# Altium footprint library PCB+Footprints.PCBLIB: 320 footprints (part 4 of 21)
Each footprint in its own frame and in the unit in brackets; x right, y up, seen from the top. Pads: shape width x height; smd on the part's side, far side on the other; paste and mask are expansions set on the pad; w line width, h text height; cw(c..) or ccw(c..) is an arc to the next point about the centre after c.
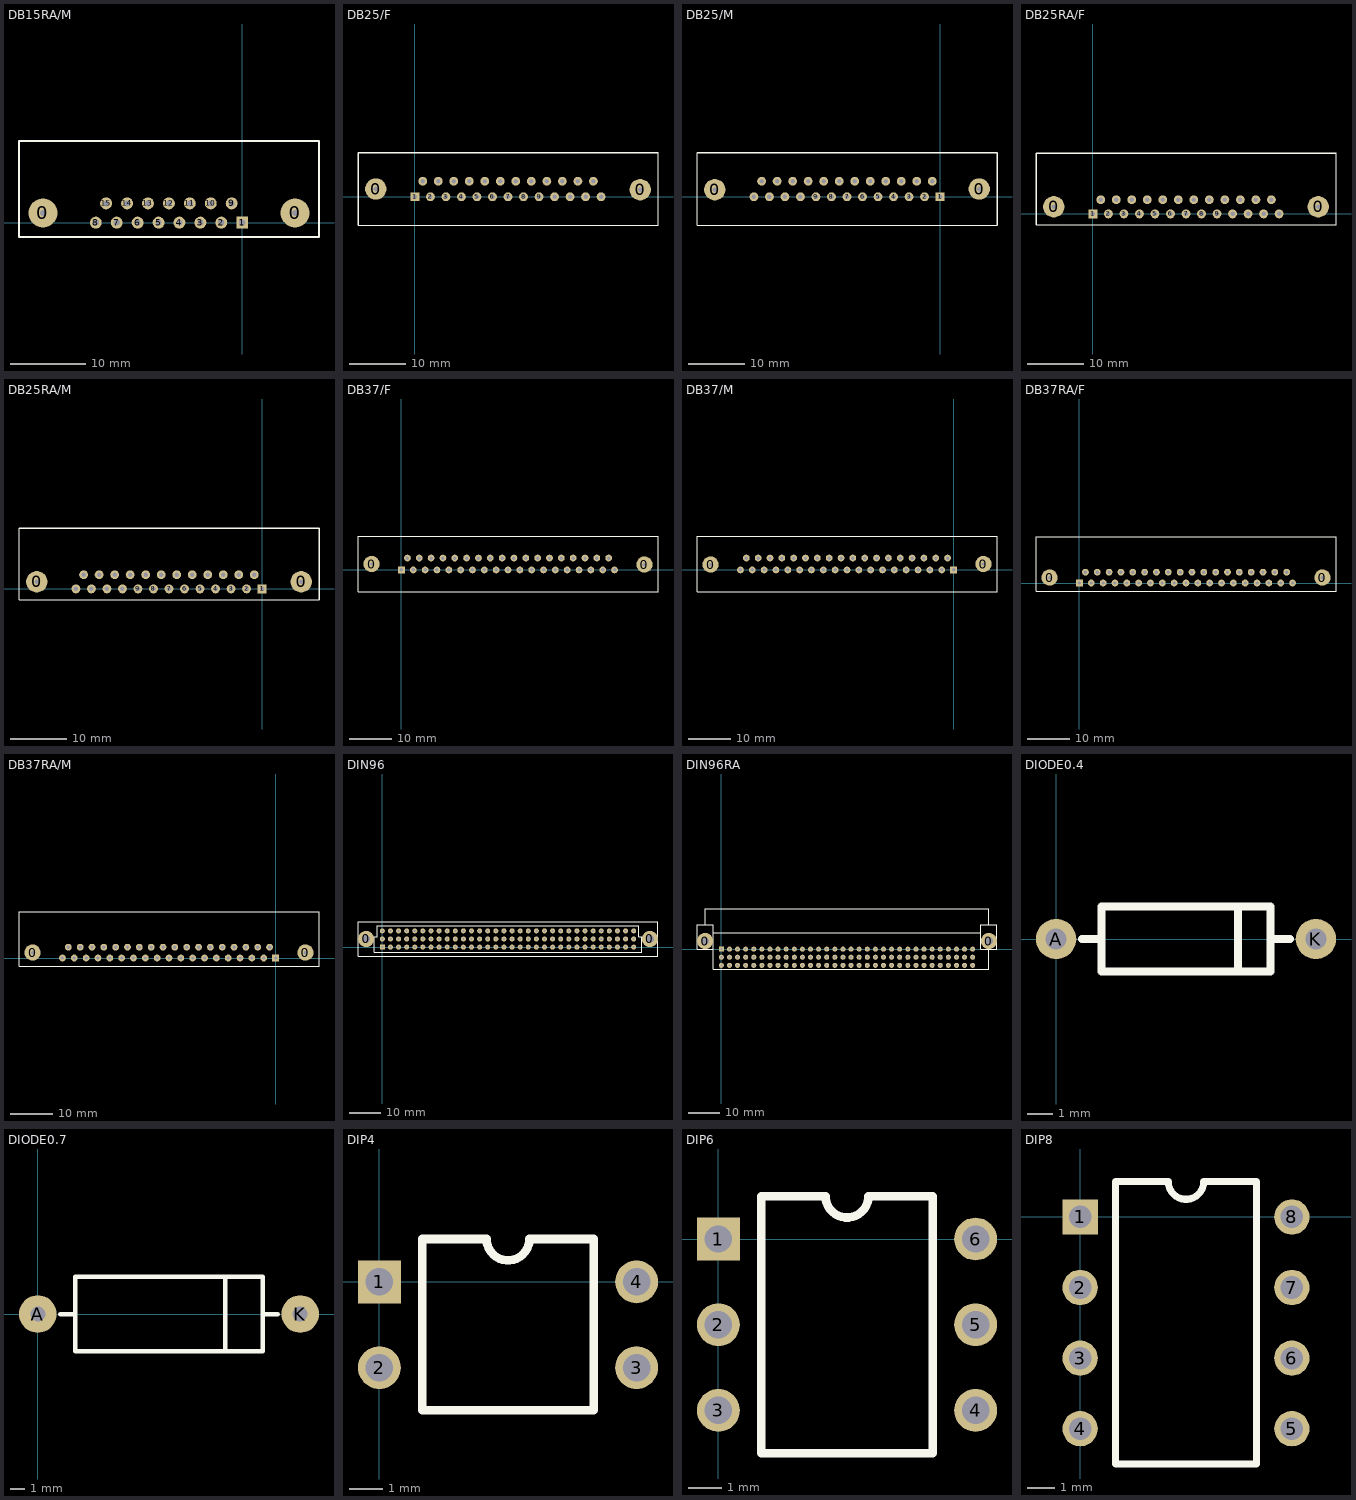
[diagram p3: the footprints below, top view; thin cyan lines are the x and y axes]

## DB15RA/M [mil]
pads (17):
  round 150 hole 32: 0(-1038,50) 0(275,50)
  rect 62x62 hole 32: 1(0,0)
  round 62 hole 32: 2(-109,0) 3(-218,0) 4(-327,0) 5(-436,0) 6(-545,0) 7(-654,0) 8(-763,0) 9(-55,100) 10(-164,100) 11(-273,100) 12(-382,100) 13(-491,100) 14(-600,100) 15(-709,100)
TopOverlay:
  lines w8: -1163,425 -1163,-75 400,-75
  lines w10: -1163,425 400,425 400,-75

## DB25/F [mil]
pads (27):
  round 150 hole 32: 0(-275,55) 0(1583,50)
  rect 62x62 hole 32: 1(0,0)
  round 62 hole 32: 2(109,0) 3(218,0) 4(327,0) 5(436,0) 6(545,0) 7(654,0) 8(763,0) 9(872,0) 10(981,0) 11(1090,0) 12(1199,0) 13(1308,0) 14(55,110) 15(164,110) 16(273,110) 17(382,110) 18(491,110) 19(600,110) 20(709,110) 21(818,110) 22(927,110) 23(1036,110) 24(1145,110) 25(1254,110)
TopOverlay:
  lines w8: -400,-200 1708,-200 1708,310
  lines w10: -400,-200 -400,310 1708,310

## DB25/M [mil]
pads (27):
  round 150 hole 32: 0(-1583,50) 0(275,55)
  rect 62x62 hole 32: 1(0,0)
  round 62 hole 32: 2(-109,0) 3(-218,0) 4(-327,0) 5(-436,0) 6(-545,0) 7(-654,0) 8(-763,0) 9(-872,0) 10(-981,0) 11(-1090,0) 12(-1199,0) 13(-1308,0) 14(-55,110) 15(-164,110) 16(-273,110) 17(-382,110) 18(-491,110) 19(-600,110) 20(-709,110) 21(-818,110) 22(-927,110) 23(-1036,110) 24(-1145,110) 25(-1254,110)
TopOverlay:
  lines w8: -1708,310 -1708,-200 400,-200
  lines w10: -1708,310 400,310 400,-200

## DB25RA/F [mil]
pads (27):
  round 150 hole 32: 0(-275,50) 0(1583,50)
  rect 62x62 hole 32: 1(0,0)
  round 62 hole 32: 2(109,0) 3(218,0) 4(327,0) 5(436,0) 6(545,0) 7(654,0) 8(763,0) 9(872,0) 10(981,0) 11(1090,0) 12(1199,0) 13(1308,0) 14(55,100) 15(164,100) 16(273,100) 17(382,100) 18(491,100) 19(600,100) 20(709,100) 21(818,100) 22(927,100) 23(1036,100) 24(1145,100) 25(1254,100)
TopOverlay:
  lines w8: -400,-75 1708,-75 1708,425
  lines w10: -400,-75 -400,425 1708,425

## DB25RA/M [mil]
pads (27):
  round 150 hole 32: 0(-1583,50) 0(275,50)
  rect 62x62 hole 32: 1(0,0)
  round 62 hole 32: 2(-109,0) 3(-218,0) 4(-327,0) 5(-436,0) 6(-545,0) 7(-654,0) 8(-763,0) 9(-872,0) 10(-981,0) 11(-1090,0) 12(-1199,0) 13(-1308,0) 14(-55,100) 15(-164,100) 16(-273,100) 17(-382,100) 18(-491,100) 19(-600,100) 20(-709,100) 21(-818,100) 22(-927,100) 23(-1036,100) 24(-1145,100) 25(-1254,100)
TopOverlay:
  lines w8: -1708,425 -1708,-75 400,-75
  lines w10: -1708,425 400,425 400,-75

## DB37/F [mil]
pads (39):
  round 150 hole 32: 0(-275,55) 0(2237,50)
  rect 62x62 hole 32: 1(0,0)
  round 62 hole 32: 2(109,0) 3(218,0) 4(327,0) 5(436,0) 6(545,0) 7(654,0) 8(763,0) 9(872,0) 10(981,0) 11(1090,0) 12(1199,0) 13(1308,0) 14(1417,0) 15(1526,0) 16(1635,0) 17(1744,0) 18(1853,0) 19(1962,0) 20(55,110) 21(164,110) 22(273,110) 23(382,110) 24(491,110) 25(600,110) 26(709,110) 27(818,110) 28(927,110) 29(1036,110) 30(1145,110) 31(1254,110) 32(1363,110) 33(1472,110) 34(1581,110) 35(1690,110) 36(1799,110) 37(1908,110)
TopOverlay:
  lines w8: -400,-200 2362,-200 2362,310
  lines w10: -400,-200 -400,310 2362,310

## DB37/M [mil]
pads (39):
  round 150 hole 32: 0(-2237,50) 0(275,55)
  rect 62x62 hole 32: 1(0,0)
  round 62 hole 32: 2(-109,0) 3(-218,0) 4(-327,0) 5(-436,0) 6(-545,0) 7(-654,0) 8(-763,0) 9(-872,0) 10(-981,0) 11(-1090,0) 12(-1199,0) 13(-1308,0) 14(-1417,0) 15(-1526,0) 16(-1635,0) 17(-1744,0) 18(-1853,0) 19(-1962,0) 20(-55,110) 21(-164,110) 22(-273,110) 23(-382,110) 24(-491,110) 25(-600,110) 26(-709,110) 27(-818,110) 28(-927,110) 29(-1036,110) 30(-1145,110) 31(-1254,110) 32(-1363,110) 33(-1472,110) 34(-1581,110) 35(-1690,110) 36(-1799,110) 37(-1908,110)
TopOverlay:
  lines w8: -2362,310 -2362,-200 400,-200
  lines w10: -2362,310 400,310 400,-200

## DB37RA/F [mil]
pads (39):
  round 150 hole 32: 0(-275,50) 0(2237,50)
  rect 62x62 hole 32: 1(0,0)
  round 62 hole 32: 2(109,0) 3(218,0) 4(327,0) 5(436,0) 6(545,0) 7(654,0) 8(763,0) 9(872,0) 10(981,0) 11(1090,0) 12(1199,0) 13(1308,0) 14(1417,0) 15(1526,0) 16(1635,0) 17(1744,0) 18(1853,0) 19(1962,0) 20(55,100) 21(164,100) 22(273,100) 23(382,100) 24(491,100) 25(600,100) 26(709,100) 27(818,100) 28(927,100) 29(1036,100) 30(1145,100) 31(1254,100) 32(1363,100) 33(1472,100) 34(1581,100) 35(1690,100) 36(1799,100) 37(1908,100)
TopOverlay:
  lines w8: -400,-75 2362,-75 2362,425
  lines w10: -400,-75 -400,425 2362,425

## DB37RA/M [mil]
pads (39):
  round 150 hole 32: 0(-2237,50) 0(275,50)
  rect 62x62 hole 32: 1(0,0)
  round 62 hole 32: 2(-109,0) 3(-218,0) 4(-327,0) 5(-436,0) 6(-545,0) 7(-654,0) 8(-763,0) 9(-872,0) 10(-981,0) 11(-1090,0) 12(-1199,0) 13(-1308,0) 14(-1417,0) 15(-1526,0) 16(-1635,0) 17(-1744,0) 18(-1853,0) 19(-1962,0) 20(-55,100) 21(-164,100) 22(-273,100) 23(-382,100) 24(-491,100) 25(-600,100) 26(-709,100) 27(-818,100) 28(-927,100) 29(-1036,100) 30(-1145,100) 31(-1254,100) 32(-1363,100) 33(-1472,100) 34(-1581,100) 35(-1690,100) 36(-1799,100) 37(-1908,100)
TopOverlay:
  lines w8: -2362,425 -2362,-75 400,-75
  lines w10: -2362,425 400,425 400,-75

## DIN96 [mil]
pads (98):
  round 200 hole 100: 0(-200,100) 0(3300,100)
  rect 62x62 hole 25: 1A(0,0)
  round 62 hole 25: 1B(0,100) 1C(0,200) 2A(100,0) 2B(100,100) 2C(100,200) 3A(200,0) 3B(200,100) 3C(200,200) 4A(300,0) 4B(300,100) 4C(300,200) 5A(400,0) 5B(400,100) 5C(400,200) 6A(500,0) 6B(500,100) 6C(500,200) 7A(600,0) 7B(600,100) 7C(600,200) 8A(700,0) 8B(700,100) 8C(700,200) 9A(800,0) 9B(800,100) 9C(800,200) 10A(900,0) 10B(900,100) 10C(900,200) 11A(1000,0) 11B(1000,100) 11C(1000,200) 12A(1100,0) 12B(1100,100) 12C(1100,200) 13A(1200,0) 13B(1200,100) 13C(1200,200) 14A(1300,0) 14B(1300,100) 14C(1300,200) 15A(1400,0) 15B(1400,100) 15C(1400,200) 16A(1500,0) 16B(1500,100) 16C(1500,200) 17A(1600,0) 17B(1600,100) 17C(1600,200) 18A(1700,0) 18B(1700,100) 18C(1700,200) 19A(1800,0) 19B(1800,100) 19C(1800,200) 20A(1900,0) 20B(1900,100) 20C(1900,200) 21A(2000,0) 21B(2000,100) 21C(2000,200) 22A(2100,0) 22B(2100,100) 22C(2100,200) 23A(2200,0) 23B(2200,100) 23C(2200,200) 24A(2300,0) 24B(2300,100) 24C(2300,200) 25A(2400,0) 25B(2400,100) 25C(2400,200) 26A(2500,0) 26B(2500,100) 26C(2500,200) 27A(2600,0) 27B(2600,100) 27C(2600,200) 28A(2700,0) 28B(2700,100) 28C(2700,200) 29A(2800,0) 29B(2800,100) 29C(2800,200) 30A(2900,0) 30B(2900,100) 30C(2900,200) 31A(3000,0) 31B(3000,100) 31C(3000,200) 32A(3100,0) 32B(3100,100) 32C(3100,200)
TopOverlay:
  lines w10: -300,-110 -300,310 3400,310 3400,-110 -300,-110 ; -100,-65 -100,130 -65,130 -65,265 3165,265 3165,130 3200,130 3200,-65 -100,-65

## DIN96RA [mil]
pads (98):
  round 200 hole 100: 0(-200,100) 0(3300,100)
  rect 62x62 hole 25: 1A(0,0)
  round 62 hole 25: 1B(0,-100) 1C(0,-200) 2A(100,0) 2B(100,-100) 2C(100,-200) 3A(200,0) 3B(200,-100) 3C(200,-200) 4A(300,0) 4B(300,-100) 4C(300,-200) 5A(400,0) 5B(400,-100) 5C(400,-200) 6A(500,0) 6B(500,-100) 6C(500,-200) 7A(600,0) 7B(600,-100) 7C(600,-200) 8A(700,0) 8B(700,-100) 8C(700,-200) 9A(800,0) 9B(800,-100) 9C(800,-200) 10A(900,0) 10B(900,-100) 10C(900,-200) 11A(1000,0) 11B(1000,-100) 11C(1000,-200) 12A(1100,0) 12B(1100,-100) 12C(1100,-200) 13A(1200,0) 13B(1200,-100) 13C(1200,-200) 14A(1300,0) 14B(1300,-100) 14C(1300,-200) 15A(1400,0) 15B(1400,-100) 15C(1400,-200) 16A(1500,0) 16B(1500,-100) 16C(1500,-200) 17A(1600,0) 17B(1600,-100) 17C(1600,-200) 18A(1700,0) 18B(1700,-100) 18C(1700,-200) 19A(1800,0) 19B(1800,-100) 19C(1800,-200) 20A(1900,0) 20B(1900,-100) 20C(1900,-200) 21A(2000,0) 21B(2000,-100) 21C(2000,-200) 22A(2100,0) 22B(2100,-100) 22C(2100,-200) 23A(2200,0) 23B(2200,-100) 23C(2200,-200) 24A(2300,0) 24B(2300,-100) 24C(2300,-200) 25A(2400,0) 25B(2400,-100) 25C(2400,-200) 26A(2500,0) 26B(2500,-100) 26C(2500,-200) 27A(2600,0) 27B(2600,-100) 27C(2600,-200) 28A(2700,0) 28B(2700,-100) 28C(2700,-200) 29A(2800,0) 29B(2800,-100) 29C(2800,-200) 30A(2900,0) 30B(2900,-100) 30C(2900,-200) 31A(3000,0) 31B(3000,-100) 31C(3000,-200) 32A(3100,0) 32B(3100,-100) 32C(3100,-200)
TopOverlay:
  lines w10: -100,200 3200,200 ; 3300,0 3300,-250 -100,-250 -100,0 ; -200,300 -200,500 3300,500 3300,300 ; -200,300 -300,300 -300,0 -100,0 ; -200,300 -100,300 -100,0 ; 3300,300 3200,300 3200,0 3400,0 3400,300 3300,300

## DIODE0.4 [mil]
pads (2):
  round 62 hole 32: A(0,0) K(400,0)
TopOverlay:
  lines w12: 40,0 70,0 ; 280,-50 280,50 ; 330,0 360,0 ; 70,-50 330,-50 330,50 70,50 70,-50

## DIODE0.7 [mil]
pads (2):
  round 100 hole 40: A(0,0) K(700,0)
TopOverlay:
  lines w12: 60,0 100,0 ; 500,-100 500,100 ; 600,0 640,0 ; 100,-100 600,-100 600,100 100,100 100,-100

## DIP4 [mil]
pads (4):
  rect 50x50 hole 32: 1(0,0)
  round 50 hole 32: 2(0,-100) 3(300,-100) 4(300,0)
TopOverlay:
  lines w10: 50,50 50,50 ; 50,50 50,-150 250,-150 250,50 175,50 cw(c150,50) 125,50 50,50

## DIP6 [mil]
pads (6):
  rect 50x50 hole 32: 1(0,0)
  round 50 hole 32: 2(0,-100) 3(0,-200) 4(300,-200) 5(300,-100) 6(300,0)
TopOverlay:
  lines w10: 50,50 50,50 ; 50,50 50,-250 250,-250 250,50 175,50 cw(c150,50) 125,50 50,50

## DIP8 [mil]
pads (8):
  rect 50x50 hole 32: 1(0,0)
  round 50 hole 32: 2(0,-100) 3(0,-200) 4(0,-300) 5(300,-300) 6(300,-200) 7(300,-100) 8(300,0)
TopOverlay:
  lines w10: 50,50 50,50 ; 50,50 50,-350 250,-350 250,50 175,50 cw(c150,50) 125,50 50,50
